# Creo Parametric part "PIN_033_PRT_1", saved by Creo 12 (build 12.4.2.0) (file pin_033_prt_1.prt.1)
Units: Custom; MM, KILOGRAM, SECS

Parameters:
  PTC_WM_ITERATION = "0"
  PTC_WM_VERSION = "-.0"
  PTC_WM_LIFECYCLE_STATE = "In Work"
  PTC_WM_LIFECYCLE = "MO_CADDocument"
  PTC_WM_CREATED_BY = "Maximilian Roepper (Z0017RMS: MO)"
  PTC_WM_CREATED_ON = "18-Sep-26 11:36:42 AM"
  PTC_WM_MODIFIED_BY = "Maximilian Roepper (Z0017RMS: MO)"
  PTC_WM_MODIFIED_ON = "18-Sep-26 11:36:46 AM"
  PDMLINKNUMBER = "PDM000071454869"
  PTC_WM_NAME = "pin_033_prt_1.prt"
  PTC_WM_NUMBER = "PDM000071454869"

Other parameters: WEIGHT, WEIGHT_FACTOR, WEIGHT_ADD, _MASS_TEMP, _DIFF_TEMP, MC_ERRORS, SUPPLIER

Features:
  1. coordinate system
  2. datum plane "PRT_YZ"
  3. datum plane "PRT_XY"
  4. datum plane "PRT_XZ"
  5. coordinate system
  6. datum axis
  7. datum axis
  8. datum axis
  9. coordinate system
  10. imported feature
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
Other named items: PRT, SIEMENS_MO, DRW_VIEW_ORG, PRT_X, PRT_Y, PRT_Z, CS0, ROUGH_GROB

Layers: 00_STD_CSYS-KSYS, 01_STD_PLANES-EBENEN, 02_STD_AXES-ACHSEN, 03_STD_CSYS-KSYS, 24_IMPORT_FEAT-IMPORT_KE

Surfaces: 9 plane, 1 cylinder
